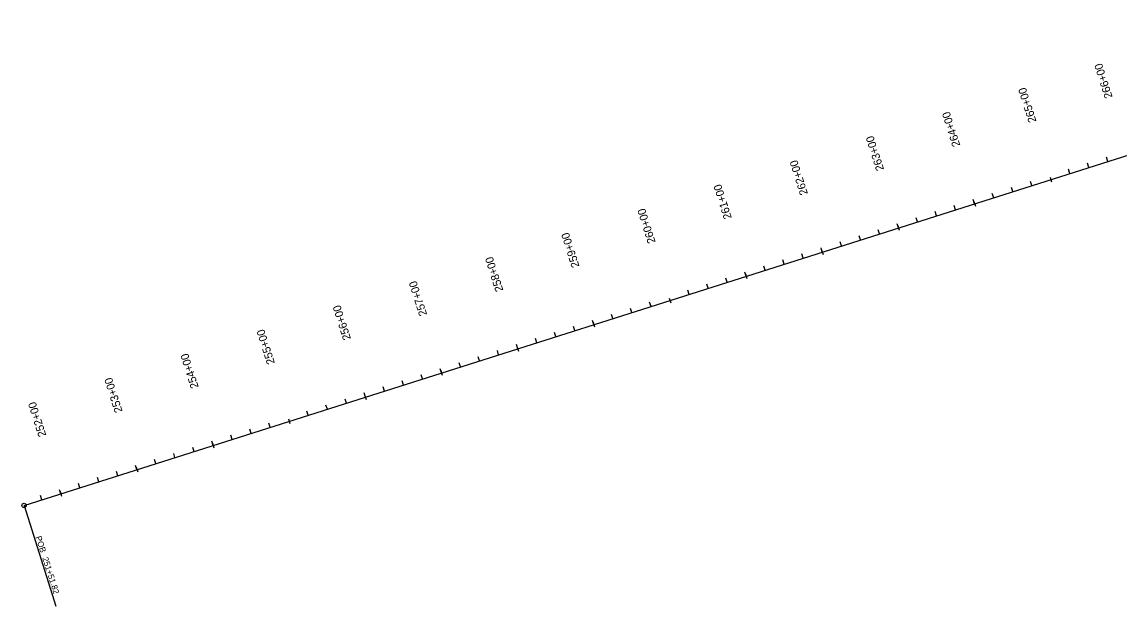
# Model space of a CAD drawing. Extents: x 20524607 to 20530050, y 8067105 to 8068411.
# Drawn here: x 20524607 to 20525980, y 8067105 to 8067836 of the extents above; entities that cross this region are included whole.
import ezdxf

# ---------------------------------------------------------------- set-up
doc = ezdxf.new("R2010")
doc.units = 0
for name, color, linetype in [('Contours Major', 7, 'Continuous'), ('Default', 7, 'Continuous'), ('Draft_DNC', 7, 'Continuous'), ('LiDAR', 7, 'Continuous'), ('Terrain', 7, 'Continuous')]:
    doc.layers.add(name, color=color, linetype=linetype)

msp = doc.modelspace()

# ---------------------------------------------------------------- linework, layer by layer
at = {"layer": 'Contours Major'}
for p, q in [((20525893.6, 8067641.5), (20525895.4, 8067635.7)), ((20525799.2, 8067608.4), (20525797.5, 8067613.6)), ((20525703.8, 8067578.2), (20525702.2, 8067583.4)), ((20525608.5, 8067547.9), (20525606.9, 8067553.1)), ((20525513.2, 8067517.7), (20525511.6, 8067522.9)), ((20525417, 8067490.3), (20525418.8, 8067484.5)), ((20525322.6, 8067457.2), (20525320.9, 8067462.4)), ((20525227.3, 8067427), (20525225.6, 8067432.2)), ((20525131.9, 8067396.7), (20525130.3, 8067401.9)), ((20525036.6, 8067366.5), (20525035, 8067371.7)), ((20524940.4, 8067339.2), (20524942.2, 8067333.3)), ((20524846, 8067306), (20524844.3, 8067311.2)), ((20524750.7, 8067275.8), (20524749, 8067281)), ((20524655.3, 8067245.5), (20524653.7, 8067250.7))]:
    msp.add_line(p, q, dxfattribs=at)
at = {"layer": 'Default'}
for q in [(20526515.8, 8067835.7), (20524609.4, 8067231)]:
    msp.add_line((20524609.4, 8067231), q, dxfattribs=at)
at = {"layer": 'Draft_DNC'}
for p in [(20524609.4, 8067231), (20524649.3, 8067105.1)]:
    msp.add_line(p, (20524649.3, 8067105.1), dxfattribs=at)
msp.add_circle((20524609.4, 8067231), 2.67, dxfattribs=at)
at = {"layer": 'LiDAR'}
for p, q in [((20525942.1, 8067653.7), (20525940.5, 8067659)), ((20525966, 8067661.3), (20525964.3, 8067666.5)), ((20525893.6, 8067641.5), (20525895.4, 8067635.7)), ((20525918.3, 8067646.2), (20525916.7, 8067651.4)), ((20525846.8, 8067623.5), (20525845.2, 8067628.7)), ((20525870.7, 8067631.1), (20525869, 8067636.3)), ((20525823, 8067615.9), (20525821.3, 8067621.2)), ((20525775.3, 8067600.8), (20525773.7, 8067606)), ((20525798.2, 8067611.3), (20525800.1, 8067605.5)), ((20525727.7, 8067585.7), (20525726, 8067590.9)), ((20525751.5, 8067593.3), (20525749.9, 8067598.5)), ((20525680, 8067570.6), (20525678.4, 8067575.8)), ((20525702.9, 8067581.1), (20525704.8, 8067575.2)), ((20525632.4, 8067555.5), (20525630.7, 8067560.7)), ((20525656.2, 8067563), (20525654.5, 8067568.2)), ((20525584.7, 8067540.4), (20525583, 8067545.6)), ((20525607.6, 8067550.8), (20525609.5, 8067545)), ((20525537, 8067525.2), (20525535.4, 8067530.4)), ((20525560.9, 8067532.8), (20525559.2, 8067538)), ((20525512.3, 8067520.6), (20525514.1, 8067514.8)), ((20525465.6, 8067502.6), (20525463.9, 8067507.8)), ((20525489.4, 8067510.1), (20525487.7, 8067515.3)), ((20525417, 8067490.3), (20525418.8, 8067484.5)), ((20525441.7, 8067495), (20525440.1, 8067500.2)), ((20525370.2, 8067472.3), (20525368.6, 8067477.5)), ((20525394.1, 8067479.9), (20525392.4, 8067485.1)), ((20525346.4, 8067464.8), (20525344.8, 8067470)), ((20525298.7, 8067449.6), (20525297.1, 8067454.8)), ((20525321.6, 8067460.1), (20525323.5, 8067454.3)), ((20525251.1, 8067434.5), (20525249.4, 8067439.7)), ((20525274.9, 8067442.1), (20525273.3, 8067447.3)), ((20525203.4, 8067419.4), (20525201.8, 8067424.6)), ((20525226.3, 8067429.9), (20525228.2, 8067424)), ((20525155.8, 8067404.3), (20525154.1, 8067409.5)), ((20525179.6, 8067411.8), (20525177.9, 8067417)), ((20525108.1, 8067389.2), (20525106.5, 8067394.4)), ((20525131, 8067399.6), (20525132.9, 8067393.8)), ((20525060.4, 8067374), (20525058.8, 8067379.2)), ((20525084.3, 8067381.6), (20525082.6, 8067386.8)), ((20525035.7, 8067369.4), (20525037.5, 8067363.6)), ((20524989, 8067351.4), (20524987.3, 8067356.6)), ((20525012.8, 8067358.9), (20525011.1, 8067364.1)), ((20524940.4, 8067339.2), (20524942.2, 8067333.3)), ((20524965.1, 8067343.8), (20524963.5, 8067349)), ((20524893.6, 8067321.1), (20524892, 8067326.3)), ((20524917.5, 8067328.7), (20524915.8, 8067333.9)), ((20524869.8, 8067313.6), (20524868.2, 8067318.8)), ((20524822.2, 8067298.4), (20524820.5, 8067303.6)), ((20524845.1, 8067308.9), (20524846.9, 8067303.1)), ((20524774.5, 8067283.3), (20524772.8, 8067288.5)), ((20524798.3, 8067290.9), (20524796.7, 8067296.1)), ((20524726.8, 8067268.2), (20524725.2, 8067273.4)), ((20524749.7, 8067278.7), (20524751.6, 8067272.8)), ((20524679.2, 8067253.1), (20524677.5, 8067258.3)), ((20524703, 8067260.6), (20524701.4, 8067265.8)), ((20524631.5, 8067238), (20524629.9, 8067243.2)), ((20524654.4, 8067248.4), (20524656.3, 8067242.6))]:
    msp.add_line(p, q, dxfattribs=at)
at = {"layer": 'Terrain'}
msp.add_line((20524609.4, 8067231), (20526515.8, 8067835.7), dxfattribs=at)

# ---------------------------------------------------------------- texts
at = {"layer": 'Contours Major'}
for s, p in [('265+00', (20525876.6, 8067711.6)), ('260+00', (20525400, 8067560.4)), ('255+00', (20524923.4, 8067409.2))]:
    msp.add_text(s, height=10.02, rotation=107.6013, dxfattribs=at).set_placement(p)
at = {"layer": 'Draft_DNC'}
for s, p in [('POB ', (20524623.7, 8067191.4)), ('251+51.82', (20524632.1, 8067165))]:
    msp.add_text(s, height=7.5, rotation=287.6013, dxfattribs=at).set_placement(p)
at = {"layer": 'LiDAR'}
for s, p in [('266+00', (20525971.9, 8067741.9)), ('265+00', (20525876.6, 8067711.6)), ('264+00', (20525781.3, 8067681.4)), ('263+00', (20525685.9, 8067651.2)), ('262+00', (20525590.6, 8067620.9)), ('261+00', (20525495.3, 8067590.7)), ('260+00', (20525400, 8067560.4)), ('259+00', (20525304.7, 8067530.2)), ('258+00', (20525209.4, 8067500)), ('257+00', (20525114, 8067469.7)), ('256+00', (20525018.7, 8067439.5)), ('255+00', (20524923.4, 8067409.2)), ('254+00', (20524828.1, 8067379)), ('253+00', (20524732.8, 8067348.8)), ('252+00', (20524637.4, 8067318.5))]:
    msp.add_text(s, height=10.02, rotation=107.6013, dxfattribs=at).set_placement(p)

doc.saveas('drawing.dxf')
